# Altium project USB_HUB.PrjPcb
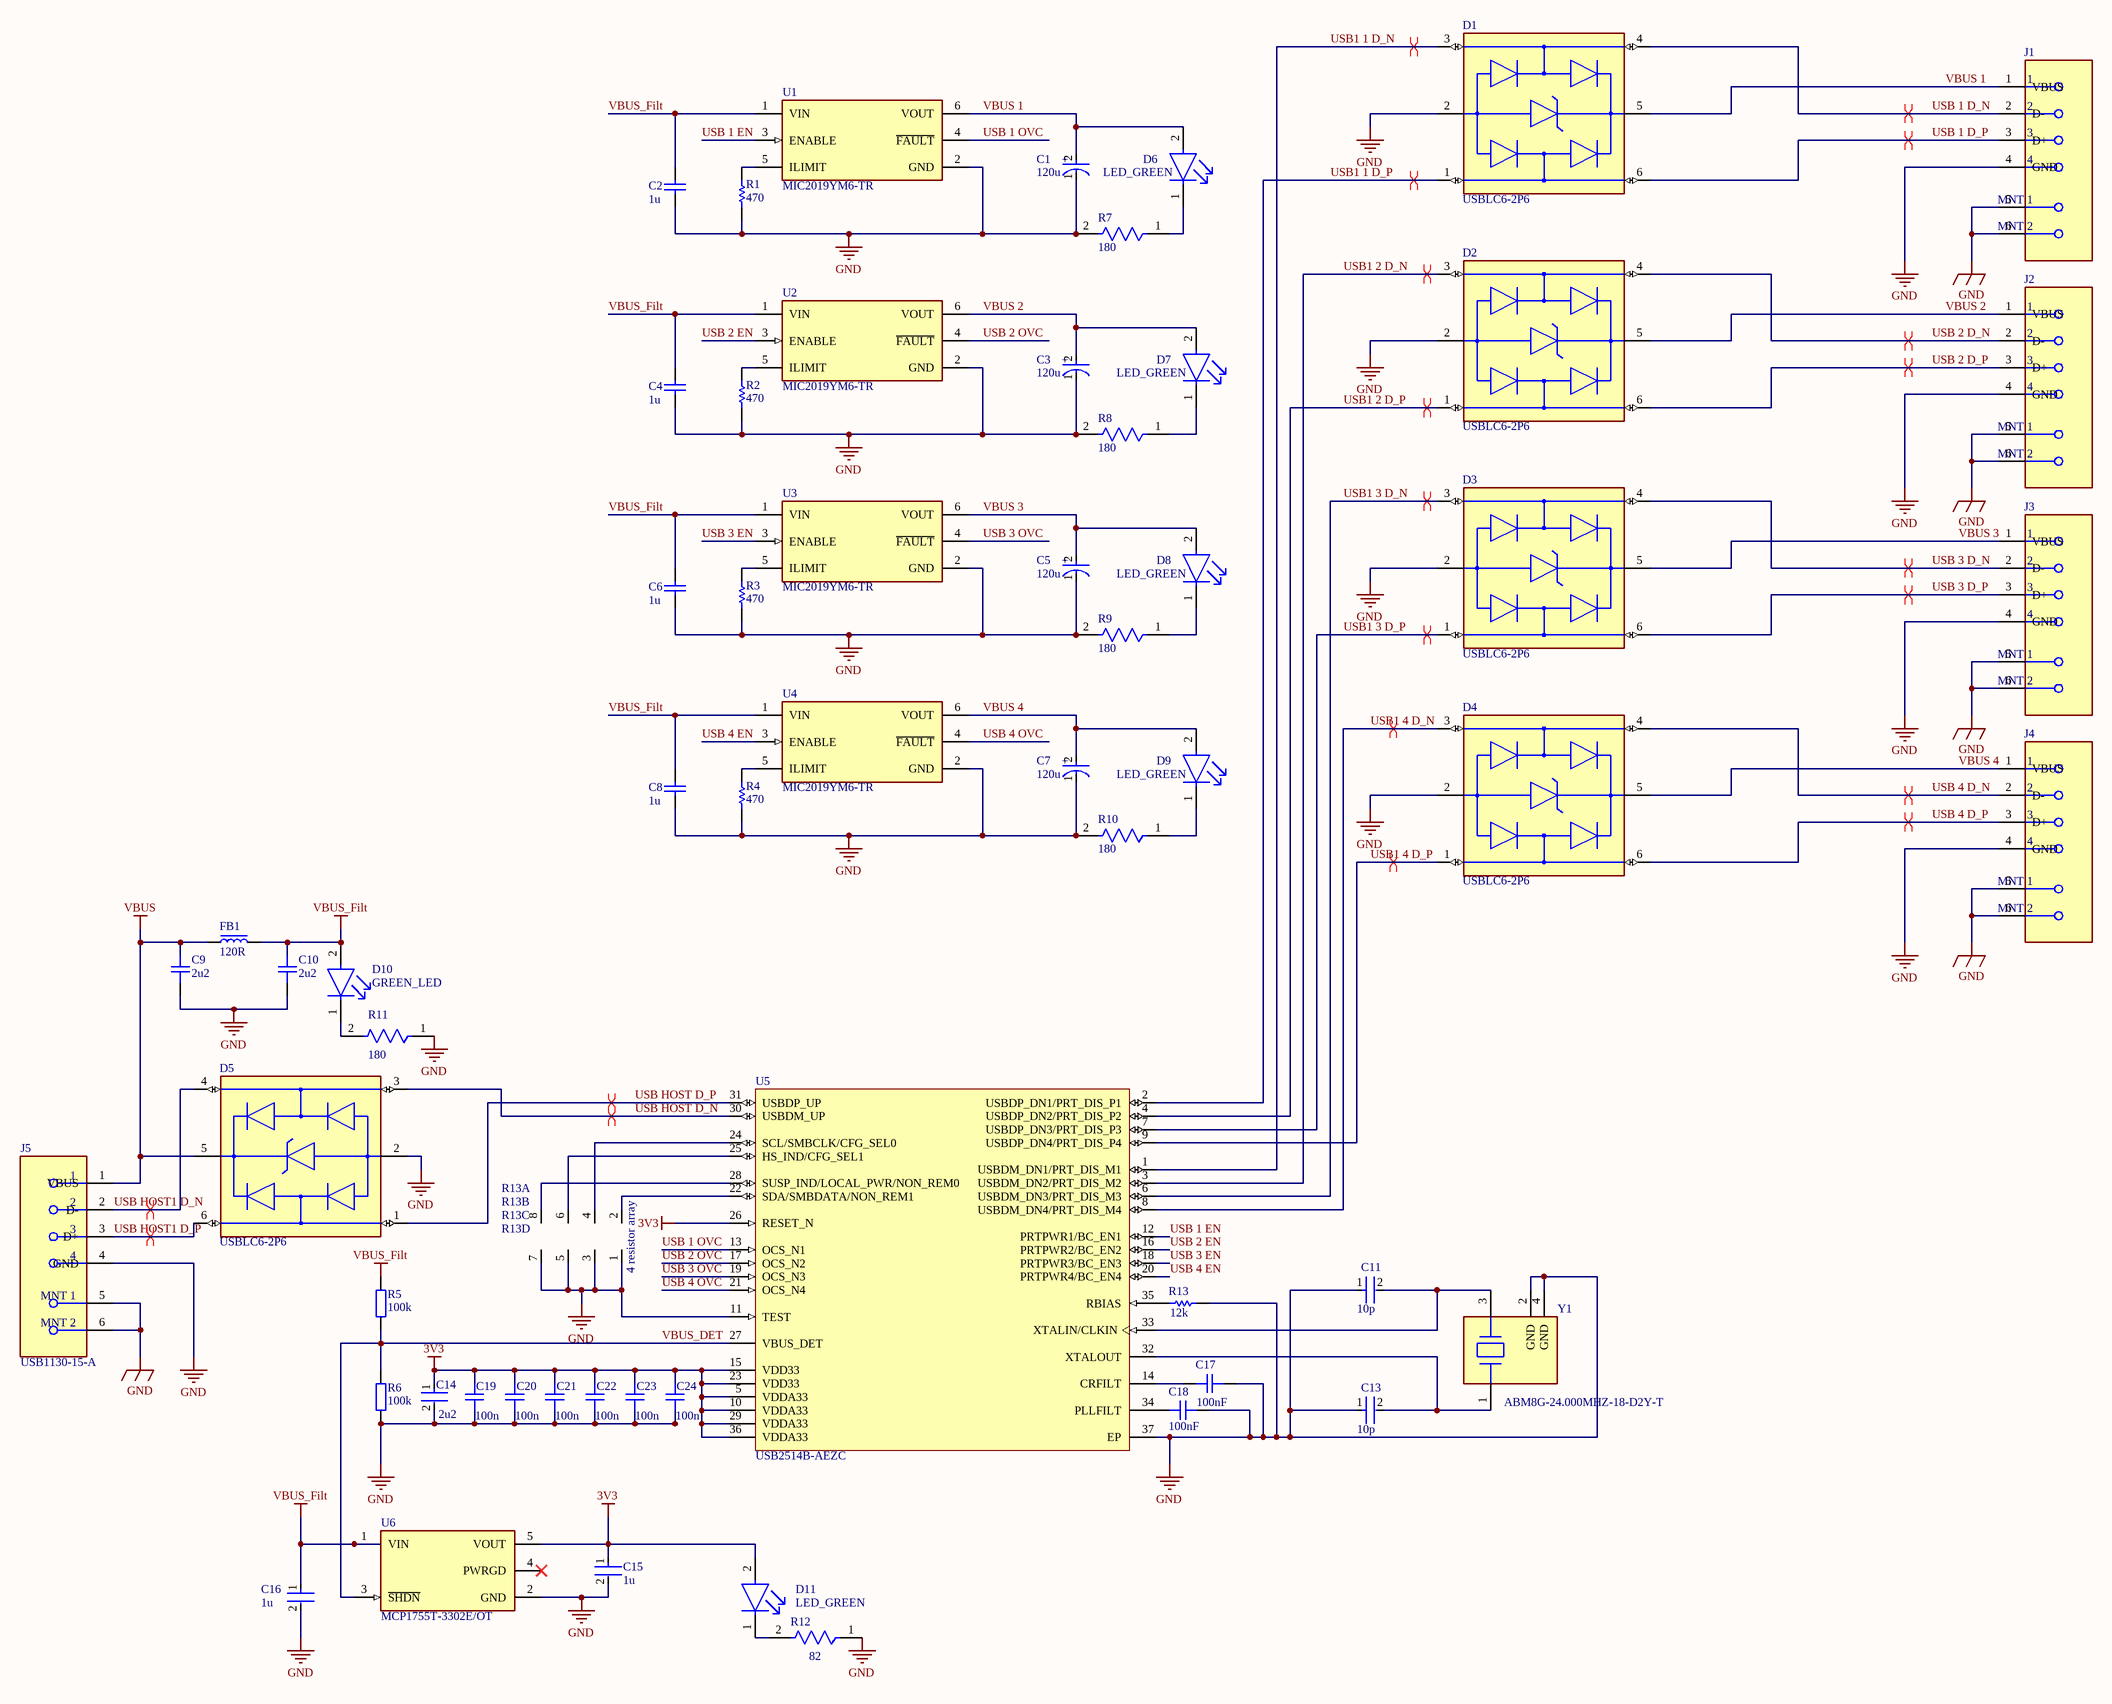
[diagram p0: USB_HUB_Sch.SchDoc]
1 sheet, 61 parts. Net scope: global (net labels, ports and power ports of the same name join across sheets).
Board file: USB_HUB_Pcb.PcbDoc

## Sheet USB_HUB_Sch.SchDoc
size A2; SheetNumber: 1; SheetTotal: 1

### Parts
(Parts that share a designator on the sheet are numbered #1, #2 ... from top to bottom, then left to right.)
C1  120u  [FP-OS-CON-SMT-E7-MFG]
C2  1u  [CAPC3216X110X50LL20T25]
C3  120u  [FP-OS-CON-SMT-E7-MFG]
C4  1u  [CAPC3216X110X50LL20T25]
C5  120u  [FP-OS-CON-SMT-E7-MFG]
C6  1u  [CAPC3216X110X50LL20T25]
C7  120u  [FP-OS-CON-SMT-E7-MFG]
C8  1u  [CAPC3216X110X50LL20T25]
C9  2u2  [CAP_0603]
C10  2u2  [CAP_0603]
C11  10p  [FP-0603-L_1_6_0_15-W_0_81-MFG]
C13  10p  [FP-0603-L_1_6_0_15-W_0_81-MFG]
C14  2u2  [FP-GRM188-0_1-e0_2_0_5-MFG]
C15  1u  [FP-0603-L_1_6_0_1-W_0_8_0-IPC_A]
C16  1u  [FP-0603-L_1_6_0_1-W_0_8_0-IPC_A]
C17  100nF  [CAP_0603]
C18  100nF  [CAP_0603]
C19  100n  [CAP_0603]
C20  100n  [CAP_0603]
C21  100n  [CAP_0603]
C22  100n  [CAP_0603]
C23  100n  [CAP_0603]
C24  100n  [CAP_0603]
D1  USBLC6-2P6  [FP-SOT-666-MFG]
D2  USBLC6-2P6  [FP-SOT-666-MFG]
D3  USBLC6-2P6  [FP-SOT-666-MFG]
D4  USBLC6-2P6  [FP-SOT-666-MFG]
D5  USBLC6-2P6  [FP-SOT-666-MFG]
D6  LED_GREEN  [FP-HSMG-C150-MFG]
D7  LED_GREEN  [FP-HSMG-C150-MFG]
D8  LED_GREEN  [FP-HSMG-C150-MFG]
D9  LED_GREEN  [FP-HSMG-C150-MFG]
D10  GREEN_LED  [FP-HSMG-C150-MFG]
D11  LED_GREEN  [FP-HSMG-C150-MFG]
FB1  120R  [FB_0603]
J1  USB1130-15-A  [FP-USB1130-15-A-MFG]  (value not drawn)
J2  USB1130-15-A  [FP-USB1130-15-A-MFG]  (value not drawn)
J3  USB1130-15-A  [FP-USB1130-15-A-MFG]  (value not drawn)
J4  USB1130-15-A  [FP-USB1130-15-A-MFG]  (value not drawn)
J5  USB1130-15-A  [FP-USB1130-15-A-MFG]
R1  470  [RESC1608X55X30ML15T15]
R2  470  [RESC1608X55X30ML15T15]
R3  470  [RESC1608X55X30ML15T15]
R4  470  [RESC1608X55X30ML15T15]
R5  100k  [RES_0603]
R6  100k  [RES_0603]
R7  180  [FP-CRCW1206-e3-IPC_C]
R8  180  [FP-CRCW1206-e3-IPC_C]
R9  180  [FP-CRCW1206-e3-IPC_C]
R10  180  [FP-CRCW1206-e3-IPC_C]
R11  180  [FP-CRCW1206-e3-IPC_C]
R12  82  [FP-CRCW1206-e3-IPC_A]
R13#1  4 resistor array  [0804]  (value not drawn)  (parts A,B,C,D of 4)
R13#2  12k  [RESC1608X55X25NL10T15]
U1  MIC2019YM6-TR  [FP-SOT23-6LD-PL-1-MFG]
U2  MIC2019YM6-TR  [FP-SOT23-6LD-PL-1-MFG]
U3  MIC2019YM6-TR  [FP-SOT23-6LD-PL-1-MFG]
U4  MIC2019YM6-TR  [FP-SOT23-6LD-PL-1-MFG]
U5  USB2514B-AEZC  [MCHP-QFN-36_V]
U6  MCP1755T-3302E/OT  [FP-C04-091-OT-MFG]
Y1  ABM8G-24.000MHZ-18-D2Y-T  [FP-ABM8G-MFG]

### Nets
3V3: C14.1 C15.1 C19.2 C20.2 C21.2 C22.2 C23.2 C24.2 D11.2(A) U5.5(VDDA33) U5.10(VDDA33) U5.15(VDD33) U5.23(VDD33) U5.26(RESET_N) U5.29(VDDA33) U5.36(VDDA33) U6.5(VOUT)
GND: C1.1(C) C2.1 C3.1(C) C4.1 C5.1(C) C6.1 C7.1(C) C8.1 C9.1 C10.1 C11.1 C13.1 C14.2 C15.2 C16.2 C17.1 C18.1 C19.1 C20.1 C21.1 C22.1 C23.1 C24.1 D1.2(GND) D2.2(GND) D3.2(GND) D4.2(GND) D5.2(GND) J1.4(GND) J1.5(MNT_1) J1.6(MNT_2) J2.4(GND) J2.5(MNT_1) J2.6(MNT_2) J3.4(GND) J3.5(MNT_1) J3.6(MNT_2) J4.4(GND) J4.5(MNT_1) J4.6(MNT_2) J5.4(GND) J5.5(MNT_1) J5.6(MNT_2) R1.1 R2.1 R3.1 R4.1 R6.1 R7.2 R8.2 R9.2 R10.2 R11.1 R12.1 R13#1.1 R13#1.3 R13#1.5 R13#1.7 R13#2.2 U1.2(GND) U2.2(GND) U3.2(GND) U4.2(GND) U5.11(TEST) U5.37(EP) U6.2(GND) Y1.2(GND) Y1.4(GND)
VBUS: C9.2 D5.5(VBUS) FB1.1 J5.1(VBUS)
VBUS_Filt: C2.2 C4.2 C6.2 C8.2 C10.2 C16.1 D10.2(A) FB1.2 R5.2 U1.1(VIN) U2.1(VIN) U3.1(VIN) U4.1(VIN) U6.1(VIN)
USB1 1 D_N: D1.3(I/O2) U5.1(USBDM_DN1/PRT_DIS_M1)
USB1 1 D_P: D1.1(I/O1) U5.2(USBDP_DN1/PRT_DIS_P1)
USB1 2 D_N: D2.3(I/O2) U5.3(USBDM_DN2/PRT_DIS_M2)
USB1 2 D_P: D2.1(I/O1) U5.4(USBDP_DN2/PRT_DIS_P2)
USB1 3 D_N: D3.3(I/O2) U5.6(USBDM_DN3/PRT_DIS_M3)
USB1 3 D_P: D3.1(I/O1) U5.7(USBDP_DN3/PRT_DIS_P3)
USB1 4 D_N: D4.3(I/O2) U5.8(USBDM_DN4/PRT_DIS_M4)
USB1 4 D_P: D4.1(I/O1) U5.9(USBDP_DN4/PRT_DIS_P4)
USB 1 D_N: D1.4(I/O2) J1.2(D-)
USB 1 D_P: D1.6(I/O1) J1.3(D+)
USB 1 EN: U1.3(ENABLE) U5.12(PRTPWR1/BC_EN1)
USB 1 OVC: U1.4(~{FAULT}) U5.13(OCS_N1)
USB 2 D_N: D2.4(I/O2) J2.2(D-)
USB 2 D_P: D2.6(I/O1) J2.3(D+)
USB 2 EN: U2.3(ENABLE) U5.16(PRTPWR2/BC_EN2)
USB 2 OVC: U2.4(~{FAULT}) U5.17(OCS_N2)
USB 3 D_N: D3.4(I/O2) J3.2(D-)
USB 3 D_P: D3.6(I/O1) J3.3(D+)
USB 3 EN: U3.3(ENABLE) U5.18(PRTPWR3/BC_EN3)
USB 3 OVC: U3.4(~{FAULT}) U5.19(OCS_N3)
USB 4 D_N: D4.4(I/O2) J4.2(D-)
USB 4 D_P: D4.6(I/O1) J4.3(D+)
USB 4 EN: U4.3(ENABLE) U5.20(PRTPWR4/BC_EN4)
USB 4 OVC: U4.4(~{FAULT}) U5.21(OCS_N4)
USB HOST1 D_N: D5.4(I/O2) J5.2(D-)
USB HOST1 D_P: D5.6(I/O1) J5.3(D+)
USB HOST D_N: D5.3(I/O2) U5.30(USBDM_UP)
USB HOST D_P: D5.1(I/O1) U5.31(USBDP_UP)
VBUS 1: C1.2(A) D1.5(VBUS) D6.2(A) J1.1(VBUS) U1.6(VOUT)
VBUS 2: C3.2(A) D2.5(VBUS) D7.2(A) J2.1(VBUS) U2.6(VOUT)
VBUS 3: C5.2(A) D3.5(VBUS) D8.2(A) J3.1(VBUS) U3.6(VOUT)
VBUS 4: C7.2(A) D4.5(VBUS) D9.2(A) J4.1(VBUS) U4.6(VOUT)
VBUS_DET: R5.1 R6.2 U5.27(VBUS_DET) U6.3(~{SHDN})
NetC11_2: C11.2 U5.33(XTALIN/CLKIN) Y1.3
NetC13_2: C13.2 U5.32(XTALOUT) Y1.1
NetC17_2: C17.2 U5.14(CRFILT)
NetC18_2: C18.2 U5.34(PLLFILT)
NetD6_1: D6.1(C) R7.1
NetD7_1: D7.1(C) R8.1
NetD8_1: D8.1(C) R9.1
NetD9_1: D9.1(C) R10.1
NetD10_1: D10.1(C) R11.2
NetD11_1: D11.1(C) R12.2
NetR1_2: R1.2 U1.5(ILIMIT)
NetR2_2: R2.2 U2.5(ILIMIT)
NetR3_2: R3.2 U3.5(ILIMIT)
NetR4_2: R4.2 U4.5(ILIMIT)
NetR13#1_2: R13#1.2(rr) U5.22(SDA/SMBDATA/NON_REM1)
NetR13#1_4: R13#1.4 U5.24(SCL/SMBCLK/CFG_SEL0)
NetR13#1_6: R13#1.6 U5.25(HS_IND/CFG_SEL1)
NetR13#1_8: R13#1.8 U5.28(SUSP_IND/LOCAL_PWR/NON_REM0)
NetR13#2_1: R13#2.1 U5.35(RBIAS)

Not connected (* = marked no-connect by the designer): U6 4(PWRGD)*

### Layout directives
differential pair; differential pair class USB HOST: USB HOST D_N, USB HOST D_P
differential pair: USB1 1 D_N, USB1 1 D_P, USB1 2 D_N, USB1 2 D_P, USB1 3 D_N, USB1 3 D_P, USB1 4 D_N, USB1 4 D_P, USB 1 D_N, USB 1 D_P, USB 2 D_N, USB 2 D_P, USB 3 D_N, USB 3 D_P, USB 4 D_N, USB 4 D_P, USB HOST1 D_N, USB HOST1 D_P

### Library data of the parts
C1 C3 C5 C7 = CMP-05428-000021-2: Conductive Polymer Aluminum Solid Capacitors (OS-CON) 120uF ±20% 16V RADIAL SMT 8x6.9mm; Leakage Current: 500uA; Ripple Current: 2.9A; ESR (Equivalent Series Resistance): 27mR; Polarity: Polar; Dissipation Factor: 12%; Life (Hours): 2000Hour
C2 C4 C6 C8 = CMP-2000-06011-1: Chip Capacitor, 1 uF, +/- 10%, 50 V, -55 to 125 degC, 1206 (3216 Metric), RoHS, Tape and Reel; Manufacturer: Kemet; Case Height: 1mm; Dielectric: X7R; Voltage Rating: 50V; Capacitance: 1uF; Temperature Coefficient / Code: +/-15%; Case Length: 3.2mm; Case Width: 1.6mm; Type: SMDMLCCX7R6.3-250VDCCommericalGrade; Class: Class1; Capacitance - nF: 1000nF
C9 C10 C17-C24 = CAP_0603: Capacitor SMD 0603
C11 C13 = CMP-2006-03982-2: General Purpose Ceramic Capacitor, 0603, 10pF, 5%, NP0, 30ppm/°C, 100V; Dielectric: C0G; Insulation Resistance: 100GR
C14 = CMP-2006-02836-2: Chip Multilayer Ceramic Capacitors for General Purpose, 0603, 2.2uF, X7R, 15%, 10%, 10V
C15 C16 = CMP-2000-07259-3: None; Voltage Rating (DC): 25V; Dielectric: X7R; Capacitance: 1uF; Tolerance: 10%
D1-D5 = CMP-12225-000058-1: TVS DIODE 5.25V 17V SOT666; Min Breakdown Voltage: 6V; Power Line Protection: Yes; Element Configuration: Dual; Test Current: 1mA; Working Voltage: 5V; Number of Channels: 2; Max Reverse Leakage Current: 150nA; Direction: Unidirectional; Peak Pulse Current: 5A; Number of Elements: 1; Capacitance: 3.5pF
D6-D11 = CMP-2000-05061-2: LED GREEN DIFFUSED 1206 SMD; Manufacturer Part Number: HSMG-C150; Manufacturer: Broadcom; Led Orientation: Top View; Max Junction Temp: +95°C; Peak Emmision Wavelength: 570nm; Viewing Angle: 170°; Wavelength: 572nm; Reverse Voltage: 5V; Luminous Intensity: 15mcd; Forward Voltage: 2.2V; Power Dissipation: 65mW; Forward Current: 20mA
FB1 = FB_0603: Ferrite Bead SMD 0603
J1-J5 = CMP-03329-113685452-1: USB1130-15-A USB Connectors USB A 2.0 Skt RA High Life 15u T Hole W/Shell Stake T & R; Number of Contacts: 4; Voltage Rating: 30V; Current Rating: 3A; USB Standard: USB 2.0
R1-R4 = CMP-1012-00473-6: Chip Resistor, 470 Ohm, +/- 1%, 0.1 W, -55 to 155 degC, 0603 (1608 Metric), RoHS, Tape and Reel; Manufacturer: Panasonic; Voltage Rating: 75 V
R5 R6 = RES_0603: Resistor SMD 0603
R7-R11 = CMP-2003-01848-2: RES Thick Film, 180Ω, 1%, 0.25W, 100ppm/°C, 1206; Voltage Rating (DC): 200V; Resistance: 180R; Power Rating: 250mW
R12 = CMP-2003-02405-2: RES Thick Film, 82Ω, 1%, 0.25W, 100ppm/°C, 1206; Resistance: 82R; Max Power Dissipation: 250mW; Working Voltage: 200V
R13#2 = CMP-1659-00047-2: Chip Resistor, 12 KOhm, +/- 1%, 100 mW, -55 to 155 degC, 0603 (1608 Metric), RoHS, Tape and Reel; Resistance: 12 kohm; Power Rating: 100 mW; Voltage Rating (DC): 50 V; Case\Package: 0603
U1-U4 = CMP-06320-000027-1: IC PWR SWITCH P-CHAN 1:1 SOT23-6; Interface: On/Off; Output Voltage: 6V; On-State Resistance: 220MR; Fault Protection: Over Temperature; Max Output Current: 2A; Number of Outputs: 1; Output Configuration: High Side; Max Supply Voltage: 5.5V
U5 = CMP-2000-05217-1: USB 2.0 High-Speed Hub Controller, 4 Ports, 3 to 3.6 V, 0 to 85 degC, 36-Pin QFN, RoHS, Tray; Manufacturer: Microchip; Interface: I²CEEPROM,SMBus(2-Wire,I²C); Other Names: 638-1122; Voltage - Supply: 3V~3.6V; Current - Supply: 70mA
U6 = CMP-06324-000083-1: IC REG LINEAR 3.3V 300MA SOT23-5; Output Voltage Accuracy: 2%; Nominal Supply Current: 68uA; Number of Regulators: 1; Quiescent Current: 100uA; Power Supply Rejection Ratio (PSRR): 80dB; Min Input Voltage: 3.6V; Polarity: Positive; Max Input Voltage: 16V; Output Type: Fixed; Dropout Voltage: 300mV
Y1 = CMP-27762-003871-2: Crystal 24MHz ±20ppm (Tol) ±30ppm (Stability) 18pF FUND 60Ω 4-Pin SMD T/R; ESR (Equivalent Series Resistance): 60R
